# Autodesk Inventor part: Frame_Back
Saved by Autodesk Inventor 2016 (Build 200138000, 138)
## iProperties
Created: 2015-11
Part Number: Frame_Back
Material: Generic
Document SubType Name: Modeling
Designer: John
Density: 1 g/cm^3
Appearance: Default
Author: John
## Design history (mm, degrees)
feature "SOLID1"
body "Solid1"
